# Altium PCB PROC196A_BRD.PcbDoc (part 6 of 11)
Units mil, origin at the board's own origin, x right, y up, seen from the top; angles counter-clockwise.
Board outline 3346.45 x 4921.26 mil, 8 copper layers (Top Layer, GND1, SIG1, PWR1, PWR2, SIG2, GND2, Bottom Layer), stack 54.534 mil thick; 736 components, 498 nets, 3030 pads, 1279 vias.
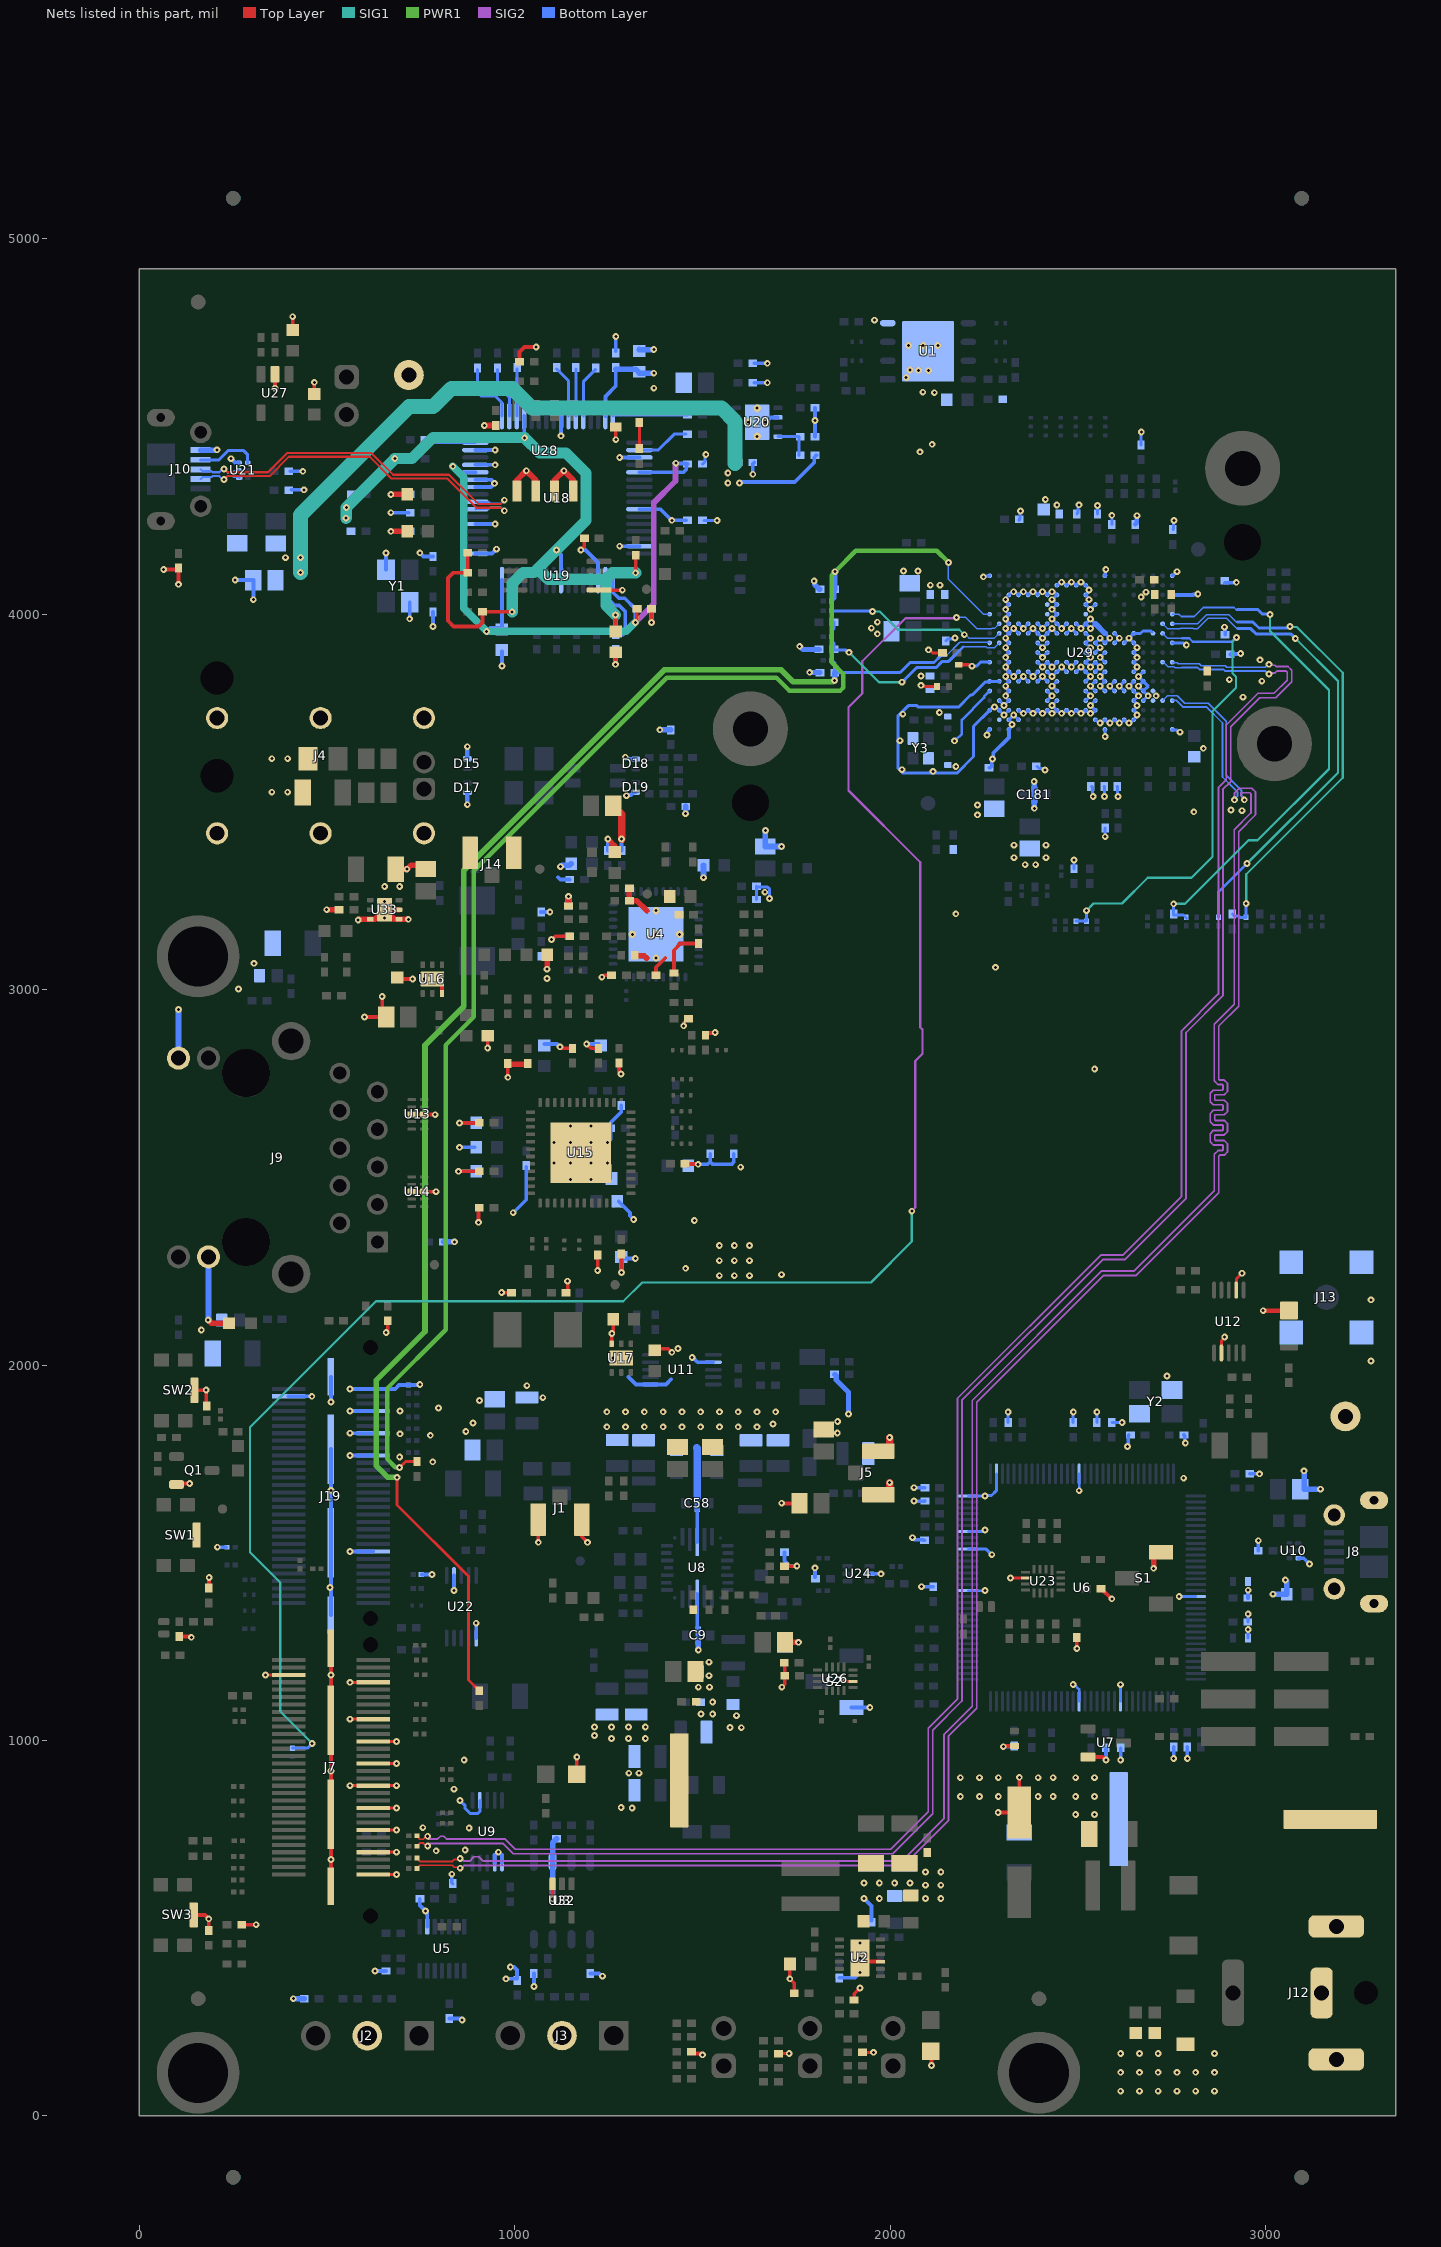
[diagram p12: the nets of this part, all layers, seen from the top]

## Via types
v1: diameter 18, hole 8, Top Layer to Bottom Layer, tented both sides, 1230 vias
v2: diameter 19.68, hole 7.87, Top Layer to Bottom Layer, 30 vias
v3: diameter 20, hole 10, Top Layer to Bottom Layer, tented both sides, 11 vias
v4: diameter 10, hole 4, SIG2 to Bottom Layer, tented both sides, 6 vias
v5: diameter 19.68, hole 7.87, Top Layer to Bottom Layer, tented both sides, 2 vias

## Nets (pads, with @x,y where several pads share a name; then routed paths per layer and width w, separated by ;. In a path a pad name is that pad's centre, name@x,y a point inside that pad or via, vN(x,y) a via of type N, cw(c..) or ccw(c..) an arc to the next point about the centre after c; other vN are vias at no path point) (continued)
FTDI_3V3: C87.1 C88.1 C89.1 C90.1 C91.1 L3.1 L4.1 R163.1 R181.2 R182.2 R184.2 R187.2 R201.2 U18.20 U18.31 U18.42 U18.50 U18.56 | length 2964.2
  Top Layer w10: R187.2@874.67,4164.3 R184.2@874.67,4110.53 835.5,4110.53 821.92,4096.95 821.92,3982.7 837.22,3967.39 903.42,3967.39 914.04,3978.01 R201.2@914.04,4006.75 v1(993.24,4006.75) ; v1(1268.73,3998.42) v1(1268.73,3998.42) C90.1@1268.76,3958.06 ; R181.2@1322.15,4153.61 1322.15,4110.61 v1(1322.22,4110.53)
  SIG1 w30: v1(550.51,4256.2) 551.26,4256.95 v1(551.26,4284.43) 680.38,4413.55 v1(680.38,4415.03) 726.22,4415.03 782.5,4471.31 1025.57,4471.31 v1(1026.57,4470.31) 1066.84,4430.04 1136.51,4430.04 1190.04,4376.52 1190.04,4250.38 v1(1111.12,4171.47) 1050.83,4111.18 1021.98,4111.18 993.24,4082.45 v1(993.24,4006.75) ; 1061.23,4121.58 1089.22,4093.59 1243.04,4093.59 ; v1(1268.73,3998.42) 1243.04,4024.11 1243.04,4093.59 ; v1(1322.22,4110.53) 1259.98,4110.53 1243.04,4093.59
  Bottom Layer w10: v1(680.38,4415.03) R163.1@717.82,4415.03 ; U18.20@1025.09,4528.19 1025.44,4527.84 1025.44,4471.44 v1(1026.57,4470.31) ; v1(1111.12,4171.47) 1123.51,4159.07 U18.56@1123.51,4091.18 ; U18.50@1241.62,4091.18 1241.62,4048.19 1266.15,4023.66 1278.4,4023.66 1294.53,4007.53 1294.53,3952.11 1288.67,3946.25 C91.1@1268.76,3946.25 ; U18.31@1241.62,4528.19 1241.62,4580.74 1269.17,4608.28 C88.1@1269.17,4653.39 ; v1(1268.73,3998.42) v1(1268.73,3998.42) C91.1@1268.76,3950.19 ; U18.42@1332.18,4280.16 1388.61,4280.16 v1(1418.39,4250.38) C89.1@1456.49,4250.38
  Bottom Layer w15: C88.1@1269.17,4653.39 1321.32,4653.39 1332.18,4642.54 v1(1370.48,4642.54)
  other v1: 1370.48,4602.54
FTDI_LDO_EN: R183.1 R204.2 U20.8 | length 105.6
  Bottom Layer w8: U20.8@1701.01,4473.42 1756.72,4473.42 R183.1@1756.72,4423.56
FTDI_MISO: R146.1 U18.18 | length 137.5
  Bottom Layer w8: R146.1@954.15,4652.62 954.15,4610 985.72,4578.44 U18.18@985.72,4528.19
FTDI_MOSI: R145.1 U18.17 | length 172.9
  Bottom Layer w8: R145.1@900.95,4652.65 900.95,4592.09 910.72,4582.33 947.43,4582.33 966.03,4563.72 U18.17@966.03,4528.19
FTDI_SPICLK: R144.1 U18.16 | length 133.4
  Bottom Layer w8: R144.1@765.07,4465.4 773.14,4457.32 U18.16@895.17,4457.32
FTDI_SPICS: R147.1 U18.19 | length 125.5
  Bottom Layer w8: U18.19@1005.4,4528.19 1005.4,4652.49 R147.1@1006.27,4653.35
FTDI_SUSPEND_N: R179.2 R180.2 | length 61.3
  Top Layer w8: R179.2@1332.18,4445.51 R180.2@1332.18,4506.81
FTDI_USBD_N: J10.2 U18.7 U21.1 | length 1029
  Top Layer w5.65: v1(225.33,4359.42) 225.91,4359.42 234.81,4368.32 346.93,4368.32 398.43,4419.81 613.58,4419.81 671.78,4361.61 820.78,4361.61 898.33,4284.06 962.68,4284.06 970.74,4276 v1(972.16,4276)
  Bottom Layer w5.65: J10.2@163.39,4360.62 168.43,4365.67 192.6,4365.67 195.25,4368.32 213.08,4368.32 221.98,4359.42 v1(225.33,4359.42) 225.91,4359.42 234.81,4368.32 249,4368.32 250.87,4366.45 263.61,4366.45 U21.1@265.99,4364.07 ; U18.7@895.17,4280.16 896.35,4281.34 931.78,4281.34 935.34,4284.9 962.68,4284.9 971.58,4276 v1(972.16,4276)
FTDI_USBD_P: J10.3 U18.8 U21.2 | length 1029.2
  Top Layer w5.65: v1(225.33,4387.42) 225.91,4387.42 234.81,4378.52 342.71,4378.52 394.2,4430.01 617.8,4430.01 676,4371.81 825,4371.81 902.55,4294.26 962.53,4294.26 972.16,4303.9 v1(972.16,4304)
  Bottom Layer w5.65: J10.3@163.39,4386.21 168.43,4381.16 192.6,4381.16 195.25,4378.52 213.08,4378.52 221.98,4387.42 v1(225.33,4387.42) 225.91,4387.42 234.81,4378.52 249,4378.52 251.85,4381.37 262.62,4381.37 U21.2@265.01,4383.75 ; U18.8@895.17,4299.84 896.35,4298.66 931.78,4298.66 935.34,4295.1 962.68,4295.1 971.58,4304 v1(972.16,4304)
FTDI_USBID: J10.4 U21.4 | length 161.5
  Bottom Layer w8: J10.4@163.39,4411.8 211.88,4411.8 236.13,4436.05 277.78,4436.05 288.63,4425.21 U21.4@288.63,4403.44
FTDI_VBUS: C39.1 C85.1 R183.2 R206.2 R207.2 U20.1 U20.2 | length 1842.6
  SIG1 w40: v1(429.39,4111.18) v1(429.39,4151.08) 429.39,4264.48 718.09,4553.18 782.4,4553.18 831.14,4601.93 993.63,4601.93 1045.37,4550.19 1550.62,4550.19 1587,4513.81 1587,4401.4
  Bottom Layer w10: v1@1598.67,4352.47 1745.8,4352.47 1797.91,4404.58 1797.91,4418.72 1802.75,4423.56 R183.2@1803.97,4423.56
  other v1: 389.39,4151.08 1567.54,4350.15 1598.67,4350.15 1567.54,4376.52
FTDI_VCORE: C77.1 C78.1 C79.1 C82.1 U18.12 U18.37 U18.49 U18.64 | length 1948.2
  Top Layer w10: v1(1321.38,3978.36) 1325.31,3982.29 C78.1@1325.31,4014.41
  SIG1 w20: v1(834.89,4394.53) 864.15,4365.27 864.15,4015.7 v1(925.28,3954.56) 1297.58,3954.56 v1(1321.38,3978.36)
  SIG2 w15: v1(1321.38,3978.36) 1370.48,4027.46 1370.48,4297.29 1428.43,4355.24 1428.43,4402.24 v1(1429,4402.81)
  Bottom Layer w10: v1(834.89,4394.53) 850.84,4378.58 U18.12@895.17,4378.58 ; v1(925.28,3954.56) 934.69,3963.97 965.97,3963.97 965.97,4091.11 U18.64@966.03,4091.18 ; U18.49@1261.31,4091.18 1261.31,4058.86 1277.42,4042.75 1293.04,4042.75 1321.38,4014.41 v1(1321.38,3978.36) ; U18.37@1332.18,4378.58 1449.8,4378.58 1457.06,4385.85 1457.06,4397.32 C82.1@1460.43,4400.69 ; v1(1429,4402.81) 1430.06,4401.75 1455.43,4401.75 C82.1@1456.49,4400.69
GND: C1.1 C2.1 C4.2 C5.1 C6.1 C7.2 C8.1 C9.2 C10.2 C11.1 C12.1 C13.1 C15.2 C16.1 C18.1 C20.1 C22.1 C23.2 C24.1 C25.2 C26.2 C27.1 C28.1 C29.2 C30.2 C31.2 C32.2 C33.2 C35.2 C36.1 C37.2 C38.2 C39.2 C40.2 C41.2 C42.1 C43.1 C44.2 C45.2 C46.1 C47.1 C48.2 C49.2 C50.2 C51.2 C52.2 C53.2 C54.1 C55.1 C56.2 C57.2 C58.2 C59.2 C60.2 C61.2 C62.2 C63.1 C64.1 C65.2 C66.1 C67.1 C68.2 C69.1 C70.2 C71.1 C72.2 C73.1 C74.1 C75.1 C76.1 C77.2 C78.2 C79.2 C80.2 C82.2 C83.2 C84.2 C85.2 C86.2 C87.2 C88.2 C89.2 C90.2 C91.2 C92.1 C93.2 C94.2 C95.2 C96.1 C97.2 C98.1 C99.2 C100.2 C101.2 C102.2 C103.2 C104.2 C105.1 C106.2 C107.1 C108.2 C109.1 C110.2 C111.1 C112.2 C113.1 C114.2 C115.1 C116.2 C117.1 C118.1 C119.2 C120.2 C121.2 C122.2 C125.2 C126.2 C127.2 C128.2 C129.2 C130.2 C131.1 C132.2 C133.2 C134.2 C135.1 C136.1 C137.1 C138.1 C139.1 C140.1 C141.1 C142.1 C143.2 C144.1 C145.2 C146.1 C147.2 C148.2 C149.1 C150.1 C151.2 C152.2 C153.1 C154.2 C155.1 C158.2 C159.2 C160.2 C163.1 C164.1 C165.1 C166.2 C167.2 C168.1 C169.2 C170.1 C171.2 C172.1 C173.1 C174.1 C175.1 C176.1 C177.1 C178.2 C180.2 C181.2 C182.2 C183.2 C184.2 C185.2 C186.2 C187.2 C188.2 C189.2 C190.2 C191.2 C192.2 C193.2 C194.2 C195.2 C196.2 C197.2 C198.2 C199.2 C200.2 C201.2 C202.2 D1.2 D3.1 D6.2 D8.2 D10.2 D12.2 D14.2 D15.2 D16.2 D17.2 D18.2 D19.2 J1.2 J1.3 J2.2 J3.2 J4.S1 J4.S2 J4.S3 J4.S4 J4.S5 J4.S6 J5.2 J5.3 J7.5 J7.8 J7.18 J7.24 J7.30 J7.36 J7.42 J7.48 J7.54 J7.60 J7.MP1 J7.MP2 J7.MP3 J7.MP4 J8.6 J8.9 J8.10 J8.11 J9.12 J9.13 J10.5 J12.2 J12.S1 J12.S2 J13.2 J14.2 J14.3 J19.16 J19.42 J19.48 J19.54 J19.57 J19.60 J19.MP1 J19.MP2 J19.MP3 J19.MP4 J21.1 J22.1 J23.1 NT1.1 NT2.2 NT3.2 NT4.2 Q1.2 R1.2 R2.1 R8.2 R10.1 R19.2 R79.1 R86.2 R89.2 R95.1 R97.1 R102.2 R110.1 R118.1 R119.2 R123.2 R126.2 R130.2 R137.1 R142.1 R143.1 R157.1 R172.1 R174.1 R175.1 R194.1 R196.2 R203.2 R204.1 R208.1 R209.1 R210.2 R251.1 R267.1 R282.1 R283.2 R285.1 R287.1 R288.1 R289.1 R292.1 R294.1 R296.2 R302.1 R303.1 R307.1 R312.1 R313.1 R314.1 R321.1 R326.1 R335.1 R337.2 R350.2 R400.2 R417.1 R512.2 S1.3 S2.3 SW1.5 SW2.5 SW3.5 TP7.1 TP9.1 U1.4 U1.9 U2.9 U2.13 U3.2 U4.37 U5.2 U6.10 U6.17 U6.48 U6.55 U6.58 U6.64 U6.66 U6.80 U6.114 U7.2 U8.12 U8.26 U9.1 U9.2 U9.7 U10.3 U11.1 U11.7 U12.2 U12.7 U13.3@725.63,2668.11 U13.8@758.51,2668.11 U14.3@725.63,2462.03 U14.8@758.51,2462.03 U15.49@1175.93,2565.54 U16.3 U16.7@780.58,3028.35 U17.3 U17.7@1283.94,2018.66 U18.1 U18.5 U18.10 U18.11 U18.13 U18.15 U18.25 U18.35 U18.47 U18.51 U19.5 U20.6 U20.9@1645.89,4511.81 U21.3 U22.1 U22.7 U23.6 U24.2 U26.6 U27.2 U28.1 U28.2 U28.3 U28.4 U29.A1 U29.A3 U29.A13 U29.A20 U29.B2 U29.B3 U29.B4 U29.B12 U29.B13 U29.B14 U29.B15 U29.B16 U29.C1 U29.C2 U29.C3 U29.C4 U29.C5 U29.C6 U29.C7 U29.C8 U29.C9 U29.C10 U29.C11 U29.C12 U29.C16 U29.D2 U29.D3 U29.D7 U29.D8 U29.D11 U29.D12 U29.D16 U29.D17 U29.D18 U29.E1 U29.E3 U29.E7 U29.E8 U29.E11 U29.E12 U29.E13 U29.E14 U29.E15 U29.E16 U29.E17 U29.E18 U29.F1 U29.F2 U29.F3 U29.F4 U29.F5 U29.F6 U29.F7 U29.F8 U29.F11 U29.F12 U29.F13 U29.F14 U29.F15 U29.F16 U29.F17 U29.G3 U29.G4 U29.G5 U29.G6 U29.G7 U29.G8 U29.G9 U29.G10 U29.G11 U29.G12 U29.G13 U29.G16 U29.G17 U29.H1 U29.H3 U29.H6 U29.H7 U29.H8 U29.H9 U29.H10 U29.H11 U29.H12 U29.H13 U29.H16 U29.J3 U29.J6 U29.J7 U29.J11 U29.J12 U29.J13 U29.J16 U29.K3 U29.K6 U29.K7 U29.K11 U29.K12 U29.K13 U29.K14 U29.K15 U29.K16 U29.K20 U29.L3 U29.L4 U29.L5 U29.L6 U29.L7 U29.L8 U29.L9 U29.L10 U29.L11 U29.L13 U29.L14 U29.L16 U29.L18 U29.M3 U29.M4 U29.M5 U29.M6 U29.M7 U29.M8 U29.M9 U29.M10 U29.M11 U29.M12 U29.N3 U29.N7 U29.N8 U29.N11 U29.P3 U29.P7 U29.P8 U29.P11 U29.P12 U29.R3 U29.R4 U29.R5 U29.R6 U29.R7 U29.R8 U29.R11 U29.R20 U29.T8 U29.T9 U29.T10 U29.T11 U29.U1 U29.U13 U29.U20 U32.3 U33.3 U33.4 U33.5 U33.7@653.41,3213.22 Y1.2 Y1.4 Y2.2 Y2.4 Y3.2 Y3.4 | length 18975.4
  Top Layer w7.5: v1(2320.48,1432.86) 2320.81,1432.53 2360.11,1432.53 U23.6@2360.3,1432.34
  Top Layer w8: v1(336.18,1174.67) J7.5@397.49,1174.67 ; v1@561.77,879.4 v1@684.4,879.4 ; v1@561.77,1056.56 J7.18@623.08,1056.56 ; v1@561.77,1154.99 J7.8@623.08,1154.99 ; J7.60@623.08,643.18 v1@684.4,643.18 ; J7.54@623.08,702.23 v1@684.4,702.23 ; J7.48@623.08,761.29 v1@684.4,761.29 ; J7.42@623.08,820.34 v1@684.4,820.34 ; J7.30@623.08,938.45 v1@684.4,938.45 ; J7.24@623.08,997.51 v1@684.4,997.51 ; R307.1@1702.27,165.74 v1(1731.14,165.74) ; v1(1871.6,1166.66) 1881.6,1156.66 U26.6@1901.26,1156.66 ; R313.1@1926.71,169.19 v1(1955.58,169.19) ; v1@2082,3807.81 C103.2@2125.25,3807.81 ; v1(2102.07,3905.43) 2104.77,3905.43 2113.37,3896.83 2138.81,3896.83 C180.2@2139.22,3897.25 ; C102.2@2182.53,3865.74 2211.37,3865.74 2215.29,3861.81 v1(2218,3861.81) ; U12.7@2882.66,2032.4 2882.66,2065.48 2891.36,2074.17 v1(2891.36,2074.78) ; U12.2@2922.03,2199.72 2922.38,2200.08 2922.38,2229.42 v1(2937.6,2244.64)
  Top Layer w10: v1(64.94,4119.21) 104.25,4119.21 v1(104.25,4079.89) ; Q1.2@99.01,1681.83 101.55,1684.36 v1(133.95,1684.36) ; C105.1@105.96,1276.96 136.4,1276.96 v1(138.5,1274.86) ; SW3.5@144.75,535.07 174.72,535.07 v1(184.83,524.96) R110.1@184.83,493.74 ; SW2.5@146.75,1932.78 v1@177.92,1932.78 ; v1(177.92,1933.44) v1@177.92,1932.78 ; R335.1@179.39,1891.44 177.92,1892.91 v1@177.92,1932.78 ; R267.1@185.16,1405.66 185.63,1406.13 185.63,1433.49 v1(186.1,1433.96) ; C128.2@276.53,509.12 v1(311.32,509.12) ; v1(361.36,4602.54) U27.2@361.36,4639.59 U27.2@361.36,4642.54 ; C145.2@408.44,4758.62 v1(408.44,4793.11) ; C149.1@466.12,4587.25 v1(466.12,4618.16) ; J7.MP4@510.29,611.09 v1(510.29,682.55) J7.MP3@510.29,803.61 v1(510.29,918.77) J7.MP2@510.29,1053.61 v1(510.29,1174.67) J7.MP1@510.29,1246.13 ; v1(599.63,2927.1) 647.02,2927.1 v1(647.02,2982.1) ; v1(657.49,2086.87) 661.43,2090.81 R118.1@661.43,2118.25 ; C48.2@687.02,3028.35 v1(728.16,3028.35) ; U14.3@725.63,2462.03 U14.8@758.51,2462.03 v1(790.24,2462.03) ; U13.3@725.63,2668.11 U13.8@758.51,2668.11 759.06,2667.55 787.45,2667.55 v1(788,2667) ; v2(802.23,3028.35) 806.17,3024.41 U16.3@806.17,2989.96 ; v1(850.52,2516.33) C188.2@901.41,2516.33 ; v1(853.06,2645.15) C189.2@901.41,2645.15 ; R337.2@901.41,2418.89 903.42,2416.88 v1(903.42,2380.25) ; v1@927.83,2842.39 v1(927.83,2844.44) R294.1@927.83,2877.21 ; C47.1@949.01,4503.22 C47.1@949.36,4503.22 ; v1(965.21,2193.37) 965.7,2192.88 987.22,2192.88 C33.2@987.71,2192.39 ; v1(981.5,2766.54) R97.1@981.5,2799.29 ; R417.1@1012.52,4672.69 1012.52,4699.22 1025.72,4712.43 v1(1057.2,4712.43) ; R137.1@1034.65,2799.29 R97.1@981.5,2799.29 ; R137.1@1034.65,2803.23 R97.1@981.5,2803.23 R97.1@981.5,2799.29 ; v1(1062.74,1527.76) J1.3@1062.74,1588.36 ; v1(1098,3133.81) 1100.16,3133.81 1108.56,3142.2 R89.2@1146.4,3142.2 ; U32.3@1100.33,617.88 1100.33,578.66 v1(1100.76,578.24) ; v1(1120.52,2847.77) 1124.45,2843.84 C160.2@1153.91,2843.84 ; v1(1140.83,2223.35) 1140.94,2223.24 C30.2@1140.94,2192.39 ; D16.2@1165.43,910.02 v1(1165.43,956.23) ; v1(1175.93,4171.47) 1185.46,4181 C86.2@1185.46,4202.72 ; J1.2@1178.88,1588.36 1178.88,1542.76 v1(1193.88,1527.76) ; v1(1191.71,2855.65) 1203.52,2843.84 C185.2@1223.15,2843.84 ; v1(1220.92,2252.12) C184.2@1220.92,2289.53 ; U19.5@1224.83,4064.47 v1(1286.74,4064.47) ; v1(1231.87,3033.39) 1236.87,3038.39 C36.1@1258.09,3038.39 ; U17.3@1258.35,2057.05 1258.35,2083.78 1262.45,2087.88 C65.2@1262.45,2122.43 ; v1(1268.76,3867.06) C90.2@1268.76,3899.01 ; v1(1269.17,4465.4) D1.2@1269.17,4499.01 ; R142.1@1277.72,2800.53 1277.72,2780.59 v1(1282.85,2775.46) ; v1@1284.2,2254.29 C191.2@1284.2,2291.7 ; C78.2@1364.68,4014.41 1364.68,3982.29 v1@1368.62,3978.36 ; C60.2@1373.01,2043.51 1408.88,2043.51 v1(1418.47,2033.92) ; C35.2@1376.2,3038.39 1376.2,3059.97 1400.81,3084.57 ; D10.2@1424,3044.53 1424,3105.14 1439.2,3120.34 1439.2,3122.96 1439.29,3122.86 C182.2@1489.66,3122.86 ; v1(1450.06,2903.88) 1451.59,2905.41 1451.59,2913.11 1461.28,2922.81 R79.1@1463.25,2922.81 ; C158.2@1453.86,2536.83 1454.86,2535.83 1487.63,2535.83 v1(1488.63,2534.83) ; R302.1@1471.02,171.07 1475.86,166.23 1494.15,166.23 1497.9,162.47 v1(1500.07,162.47) ; R289.1@1508.33,2878.66 1508.33,2879.63 1513.17,2884.47 1532.47,2884.47 v1(1534,2886) ; v1(1711.33,1632.06) 1711.83,1631.56 C198.2@1758.36,1631.56 ; v1(1711.55,1141.8) 1719.33,1149.58 C18.1@1719.33,1172.28 1719.33,1205.59 R283.2@1718.06,1206.86 ; R102.2@1718.74,1464.28 1718.8,1464.33 1751.57,1464.33 v1(1751.63,1464.39) ; C10.2@1732.73,404.47 v1(1732.73,365.1) 1744.54,353.29 R1.2@1744.54,326.87 ; R10.1@1904.25,308.55 1904.25,324.99 v1(1919.6,340.34) ; v2(1919.6,420.63) 1929.45,410.79 U2.9@1974.33,410.79 ; v1(2053,4651) v1@2053.5,4650.5 ; D12.2@2108.41,172.26 2110.15,170.52 v1(2110.15,134.17) ; v1(2287.98,808.05) C99.2@2344.16,808.05 v1(2344.16,901.82) ; v1(2301.76,983.22) 2303.71,985.16 C41.2@2330.38,985.16 ; v1@2497.52,1247.58 R296.2@2497.52,1274.04 ; U7.2@2527.23,956.1 2566.82,956.1 v1(2574.86,948.06) ; C98.1@2561.5,1403.8 2563.47,1403.8 2589.96,1377.31 v1(2590.79,1377.31)
  Top Layer w12: v1(2994,2144.81) 3062.14,2144.81 D6.2@3062.49,2145.16
  Top Layer w14: J5.2@1968.94,1770.93 1985.33,1770.93 J5.2@1999,1784.6
  Top Layer w15: v1(183.25,2119.9) 191.73,2111.42 D8.2@238.49,2111.42 ; v1(499.02,3213.22) R314.1@531.97,3213.22 ; v1(583.05,3185.43) 585.02,3187.4 587.09,3187.4 587.32,3187.63 U33.3@615.03,3187.63 627.82,3187.63 U33.7@653.41,3213.22 ; C197.2@669.98,3320.94 C197.2@683.13,3320.94 v1(712.61,3320.94) 723.59,3331.92 C196.2@763.1,3331.92 ; v1(669.98,4221.1) C68.2@713.89,4221.1 ; v1(669.98,4319.53) C72.2@713.89,4319.53 ; U33.5@691.8,3213.22 U33.7@653.41,3213.22 ; v1(716.55,3187.63) U33.4@691.8,3187.63 679,3187.63 U33.7@653.41,3213.22 ; v1(918.87,4503.22) C47.1@949.01,4503.22 ; U28.1@1005.83,4328.56 1005.83,4357.56 v1(1030.83,4382.56) 1055.83,4357.56 U28.2@1055.83,4328.56 ; v1(1086.18,3054.55) 1086.18,3056.06 1086.47,3056.35 C32.2@1086.47,3092.81 ; U28.3@1105.83,4328.56 1105.83,4357.56 v1(1130.83,4382.56) 1155.83,4357.56 U28.4@1155.83,4328.56 ; R350.2@1143.2,3222.97 v1(1143.2,3248.95) ; v1(1248.1,3401.21) 1266.14,3383.17 C147.2@1266.14,3366.46 ; C148.2@1305.51,3270.67 1305.51,3237.19 C154.2@1305.96,3236.75 1325.41,3236.75 1351.6,3210.56 ; D14.2@1319.63,3091.95 1320.72,3090.85 1344.05,3090.85 1350.33,3084.57 1351.6,3084.57 ; C120.2@1719.91,1261.41 v1(1756.11,1261.41) ; v1(2702.21,1458.6) 2702.21,1489.05 2714.4,1501.24 S1.3@2721.56,1501.24
  Top Layer w20: C122.2@1262.52,3489.89 1284.68,3467.73 v1(1284.68,3401.21) ; J5.3@1968.94,1654.79 1988.33,1654.79 1999,1665.46 v1(1999,1686.81) ; J5.2@1999,1784.6 v1(1999,1806.81)
  Bottom Layer w7: v1@2169.91,3664.72 2174.67,3664.72 2191.1,3681.16 2191.1,3719 2250.58,3778.48 2250.58,3781.16 U29.E1@2265.3,3795.89 ; U6.48@2208.34,1399.28 v1(2252.92,1399.28) ; v1@2487.86,1149.79 2489.39,1149.79 2503.61,1135.57 U6.17@2503.61,1104.01 ; v1(2503.61,1665.52) U6.80@2503.61,1710.31 ; U6.10@2613.85,1104.01 v1@2613.85,1147.29 ; v1@2771.35,1383.54 U6.114@2814.64,1383.54
  Bottom Layer w8: v1(854.27,840) 867.99,826.27 867.99,818.81 880.8,806 902.44,806 907.05,810.61 U9.7@907.05,840.58 ; C82.2@1499.8,4400.69 1500.91,4400.69 1506.6,4406.38 1506.6,4420.79 1509,4423.19 v1(1509,4425.81) ; C89.2@1503.74,4250.38 1503.83,4250.29 1539.14,4250.29 v1(1539.24,4250.19) ; C44.2@1643.95,3240.41 C46.1@1643.95,3275.88 1646.52,3273.31 1673.88,3273.31 1678.57,3268.62 v1(1678.57,3242.67) ; C115.1@2148.52,3929.27 2154.14,3934.9 2171.09,3934.9 v1(2173,3936.81) ; U6.55@2208.34,1509.52 2256.01,1509.52 2270.72,1494.81 v1(2271,1494.81) ; U6.58@2208.34,1556.77 2248.92,1556.77 v1(2252.92,1560.77) ; U6.64@2208.34,1651.25 v1(2252.92,1651.25) 2254.2,1652.53 2270.11,1652.53 2283.03,1665.45 2283.03,1682.64 2283.14,1682.75 U6.66@2283.14,1710.31 ; v1(2218,3861.81) 2218.7,3862.51 2230.99,3862.51 2241.14,3872.66 U29.H1@2265.3,3872.66 ; v1(2248.33,4100) 2250.21,4101.88 2263.83,4101.88 U29.U1@2265.3,4103.34 ; U29.D2@2290.89,3770.29 v1(2303.69,3757.5) U29.D3@2316.48,3770.29 2308.06,3778.72 v1(2308.06,3783.09) 2308.06,3787.46 U29.E3@2316.48,3795.89 2308.06,3804.31 v1(2308.06,3808.68) 2308.06,3813.05 U29.F3@2316.48,3821.48 2308.06,3829.9 v1(2308.06,3834.27) 2308.06,3838.64 U29.G3@2316.48,3847.07 ; U29.F2@2290.89,3821.48 U29.F1@2265.3,3821.48 2264.21,3820.38 2254.13,3820.38 2218.62,3784.87 2214.06,3784.87 2182,3752.81 2075.36,3752.81 2071.36,3756.81 2048.46,3756.81 2020.46,3728.81 2020.46,3591.21 2034.86,3576.81 2178,3576.81 2222.31,3621.12 2222.31,3701.72 U29.C1@2265.3,3744.7 2273.72,3753.13 v1(2278.1,3753.13) 2282.47,3753.13 U29.C2@2290.89,3744.7 v1(2303.69,3731.91) U29.C3@2316.48,3744.7 ; C49.2@2314.64,1847.1 v1(2314.64,1874.81) ; U29.A3@2316.48,3693.52 2324.91,3701.95 2324.91,3710.69 U29.B3@2316.48,3719.11 v1(2329.28,3731.91) U29.B4@2342.07,3719.11 ; U29.C4@2342.07,3744.7 2350.5,3736.28 v1(2354.87,3736.28) 2359.24,3736.28 U29.C5@2367.66,3744.7 2376.09,3736.28 v1(2380.46,3736.28) 2384.83,3736.28 U29.C6@2393.25,3744.7 2401.68,3736.28 v1(2406.05,3736.28) 2410.42,3736.28 U29.C7@2418.84,3744.7 2427.27,3736.28 v1(2431.64,3736.28) 2436.01,3736.28 U29.C8@2444.43,3744.7 ; U29.F4@2342.07,3821.48 v1(2354.87,3834.27) U29.F5@2367.66,3821.48 ; U29.G4@2342.07,3847.07 v1(2329.28,3834.27) U29.G3@2316.48,3847.07 ; U29.L4@2342.07,3949.43 v1(2329.28,3962.22) U29.L3@2316.48,3949.43 ; U29.M4@2342.07,3975.02 v1(2354.87,3962.22) U29.M5@2367.66,3975.02 ; C150.1@2343.16,4249.83 C150.1@2345.15,4251.81 ; C150.1@2343.97,4253 2345.62,4254.66 2345.62,4273.93 v1(2347.28,4275.59) ; U29.G5@2367.66,3847.07 v1(2380.46,3834.27) U29.G6@2393.25,3847.07 ; U29.L5@2367.66,3949.43 v1(2380.46,3962.22) U29.L6@2393.25,3949.43 v1(2406.05,3936.63) U29.L7@2418.84,3949.43 v1(2431.64,3962.22) U29.L8@2444.43,3949.43 ; C117.1@2391.37,3595.05 2397.19,3589.24 2406.29,3589.24 2410.11,3585.42 v1(2412.82,3585.42) ; U29.F6@2393.25,3821.48 v1(2406.05,3834.27) U29.F7@2418.84,3821.48 ; U29.H6@2393.25,3872.66 v1(2406.05,3859.86) U29.H7@2418.84,3872.66 v1(2431.64,3859.86) U29.H8@2444.43,3872.66 ; U29.J6@2393.25,3898.25 v1(2406.05,3885.45) U29.J7@2418.84,3898.25 ; U29.K6@2393.25,3923.84 v1(2406.05,3911.04) U29.K7@2418.84,3923.84 ; U29.M6@2393.25,3975.02 v1(2406.05,3962.22) U29.M7@2418.84,3975.02 ; U29.D7@2418.84,3770.29 v1(2431.64,3783.09) U29.E7@2418.84,3795.89 ; U29.G7@2418.84,3847.07 v1(2431.64,3834.27) U29.G8@2444.43,3847.07 v1(2457.23,3859.86) U29.G9@2470.03,3847.07 ; U29.D8@2444.43,3770.29 v1(2431.64,3757.5) U29.C8@2444.43,3744.7 ; U29.E8@2444.43,3795.89 v1(2431.64,3808.68) U29.F8@2444.43,3821.48 ; U29.T8@2444.43,4077.38 2452.86,4085.81 v1(2457.23,4085.81) 2461.6,4085.81 U29.T9@2470.03,4077.38 2478.45,4085.81 v1(2482.82,4085.81) 2487.19,4085.81 U29.T10@2495.62,4077.38 2504.04,4085.81 v1(2508.41,4085.81) 2512.78,4085.81 U29.T11@2521.21,4077.38 2529.63,4068.96 v1(2529.63,4064.59) 2529.63,4060.21 U29.R11@2521.21,4051.79 2529.63,4043.37 v1(2529.63,4039) 2529.63,4034.62 U29.P11@2521.21,4026.2 v1(2534,4013.4) U29.P12@2546.8,4026.2 ; U29.H9@2470.03,3872.66 v1(2482.82,3859.86) U29.H10@2495.62,3872.66 ; U29.L9@2470.03,3949.43 v1(2482.82,3962.22) U29.L10@2495.62,3949.43 ; U29.M9@2470.03,3975.02 v1(2457.23,3962.22) U29.M8@2444.43,3975.02 v1(2431.64,3987.81) U29.N8@2444.43,4000.61 v1(2431.64,4013.41) U29.P8@2444.43,4026.2 v1(2431.64,4039) U29.R8@2444.43,4051.79 2436.01,4060.21 v1(2431.64,4060.21) 2427.27,4060.21 U29.R7@2418.84,4051.79 2410.42,4060.21 v1(2406.05,4060.21) 2401.68,4060.21 U29.R6@2393.25,4051.79 2384.83,4060.21 v1(2380.46,4060.21) 2376.09,4060.21 U29.R5@2367.66,4051.79 2359.24,4060.21 v1(2354.87,4060.21) 2350.5,4060.21 U29.R4@2342.07,4051.79 2333.65,4060.21 v1(2329.28,4060.21) 2324.91,4060.21 U29.R3@2316.48,4051.79 2308.06,4043.37 v1(2308.06,4039) 2308.06,4034.62 U29.P3@2316.48,4026.2 2308.06,4017.78 v1(2308.06,4013.4) 2308.06,4009.03 U29.N3@2316.48,4000.61 2308.06,3992.19 v1(2308.06,3987.81) 2308.06,3983.44 U29.M3@2316.48,3975.02 2308.06,3966.59 v1(2308.06,3962.22) 2308.06,3957.85 U29.L3@2316.48,3949.43 ; C42.1@2487.6,1847.1 2487.8,1847.3 2487.8,1874.61 v1(2488,1874.81) ; R303.1@2489.92,3322.25 2489.96,3322.29 v1(2489.96,3345.77) ; U29.G10@2495.62,3847.07 v1(2508.41,3859.86) U29.G11@2521.21,3847.07 v1(2534,3834.27) U29.F11@2521.21,3821.48 ; U29.M10@2495.62,3975.02 v1(2508.41,3962.22) U29.M11@2521.21,3975.02 ; C92.1@2497.58,4267.83 2501.09,4271.34 2501.09,4289.9 v1(2503,4291.81) ; U29.D11@2521.21,3770.29 v1(2534,3783.09) U29.E11@2521.21,3795.89 ; U29.L11@2521.21,3949.43 v1(2534,3936.63) U29.K11@2521.21,3923.84 v1(2534,3911.04) U29.J11@2521.21,3898.25 v1(2534,3885.45) U29.H11@2521.21,3872.66 v1(2534,3859.86) U29.H12@2546.8,3872.66 v1(2559.59,3859.86) U29.G12@2546.8,3847.07 ; C140.1@2537.04,3541.71 2539.09,3539.67 2539.09,3516.72 v1(2541,3514.81) ; U29.B12@2546.8,3719.11 2555.22,3710.69 v1(2559.59,3710.69) 2563.96,3710.69 U29.B13@2572.39,3719.11 2580.81,3710.69 v1(2585.18,3710.69) 2589.55,3710.69 U29.B14@2597.98,3719.11 2606.4,3710.69 v1(2610.77,3710.69) 2615.14,3710.69 U29.B15@2623.57,3719.11 2631.99,3710.69 v1(2636.36,3710.69) 2640.74,3710.69 2657.58,3727.54 v1(2657.58,3731.91) 2657.58,3736.28 U29.C16@2649.16,3744.7 2657.58,3753.13 v1(2657.58,3757.5) 2657.58,3761.87 U29.D16@2649.16,3770.29 v1(2661.96,3783.09) U29.E16@2649.16,3795.89 ; U29.D12@2546.8,3770.29 v1(2534,3757.5) U29.C12@2546.8,3744.7 2538.37,3736.28 v1(2534,3736.28) 2529.63,3736.28 U29.C11@2521.21,3744.7 2512.78,3736.28 v1(2508.41,3736.28) 2504.04,3736.28 U29.C10@2495.62,3744.7 2487.19,3736.28 v1(2482.82,3736.28) 2478.45,3736.28 U29.C9@2470.03,3744.7 2461.6,3736.28 v1(2457.23,3736.28) 2452.86,3736.28 U29.C8@2444.43,3744.7 ; U29.E12@2546.8,3795.89 v1(2534,3808.68) U29.F12@2546.8,3821.48 ; U29.J12@2546.8,3898.25 v1(2559.59,3911.04) U29.K12@2546.8,3923.84 v1(2559.59,3936.63) U29.K13@2572.39,3923.84 v1(2585.18,3936.63) U29.L13@2572.39,3949.43 ; C74.1@2550.86,1847.1 v1(2550.86,1874.81) ; C164.1@2552.55,4267.83 v1(2552.55,4289.88) ; C163.1@2570.08,3541.71 2570.54,3541.25 2570.54,3515.27 v1(2571,3514.81) ; U29.A13@2572.39,3693.52 2572.69,3693.22 2572.69,3675.12 v1(2573,3674.81) ; U29.E13@2572.39,3795.89 v1(2559.59,3808.68) U29.F13@2572.39,3821.48 v1(2559.59,3834.27) U29.G13@2572.39,3847.07 ; U29.H13@2572.39,3872.66 v1(2559.59,3885.45) U29.J13@2572.39,3898.25 ; R312.1@2572.88,3430.44 2572.95,3430.37 2572.95,3407.78 v1(2573.02,3407.71) ; C75.1@2590.64,1847.1 v1(2618.35,1847.1) ; C174.1@2590.78,4239.83 v1(2590.78,4263.81) ; U29.E14@2597.98,3795.89 v1(2585.18,3808.68) U29.F14@2597.98,3821.48 ; U29.K14@2597.98,3923.84 v1(2610.77,3936.63) U29.L14@2597.98,3949.43 ; C175.1@2605.12,3541.71 2606.06,3540.77 2606.06,3515.75 v1(2607,3514.81) ; U29.E15@2623.57,3795.89 v1(2610.77,3808.68) U29.F15@2623.57,3821.48 ; U29.K15@2623.57,3923.84 v1(2636.36,3936.63) ; U29.E16@2649.16,3795.89 v1(2636.36,3808.68) U29.F16@2649.16,3821.48 ; U29.G16@2649.16,3847.07 2657.58,3855.49 v1(2657.58,3859.86) 2657.58,3864.23 U29.H16@2649.16,3872.66 2657.58,3881.08 v1(2657.58,3885.45) 2657.58,3889.82 U29.J16@2649.16,3898.25 2657.58,3906.67 v1(2657.58,3911.04) 2657.58,3915.41 U29.K16@2649.16,3923.84 v1(2636.36,3936.63) ; R326.1@2668.4,4451.58 2668.75,4451.94 2668.75,4485.39 v1(2669.11,4485.75) ; U29.D17@2674.75,3770.29 v1(2687.55,3783.09) U29.E17@2674.75,3795.89 ; U29.G17@2674.75,3847.07 v1(2661.95,3834.27) U29.F17@2674.75,3821.48 ; U29.L18@2697.55,3953.5 2695.33,3955.72 2673.67,3955.72 2667.38,3949.43 U29.L16@2649.16,3949.43 v1(2636.36,3936.63) ; U29.A20@2751.52,3693.52 2752.62,3692.43 2763.36,3692.43 2769.78,3686 v1(2772.49,3686) ; U29.K20@2751.52,3923.84 2752.05,3923.31 2782.28,3923.31 2786.54,3919.05 v1@2789.82,3919.05 ; U29.U20@2751.52,4102.97 2752.75,4102.97 2763.36,4113.58 v1(2764.59,4113.58) ; C165.1@2753.34,4225.68 2754.68,4227.02 2754.68,4248.66 v1(2756.02,4250) ; C64.1@2952.87,1315.66 2953.44,1316.23 2953.44,1336.25 v1(2954,1336.81) ; C62.2@2953.5,1272.74 2953.73,1272.96 2953.73,1295.49 v1(2953.95,1295.72) ; U29.G3@2316.48,3847.07 2308.06,3855.49 v1(2308.06,3859.86) 2308.06,3864.23 U29.H3@2316.48,3872.66 2308.06,3881.08 v1(2308.06,3885.45) 2308.06,3889.82 U29.J3@2316.48,3898.25 2308.06,3906.67 v1(2308.06,3911.04) 2308.06,3915.41 U29.K3@2316.48,3923.84 2308.06,3932.26 v1(2308.06,3936.63) 2308.06,3941 U29.L3@2316.48,3949.43 ; U29.M11@2521.21,3975.02 v1(2534,3962.22) U29.M12@2546.8,3975.02 v1(2534,3987.81) U29.M11@2521.21,3975.02 ; U29.E17@2674.75,3795.89 2687.55,3808.68 U29.F17@2674.75,3821.48 ; U29.E17@2674.75,3795.89 v1(2661.95,3808.68) U29.F17@2674.75,3821.48
  Bottom Layer w10: v1(207.63,1514.71) R321.1@231.46,1514.71 ; v1(243.95,4414.8) 254.41,4404.34 264.1,4404.34 U21.3@265.01,4403.44 ; v1(255.13,4091.18) C39.2@303.71,4091.18 303.71,4038.7 v1(303.4,4039.01) ; v1(264.08,3002.19) v1@264.25,3002.19 ; J19.57@397.49,1916.88 v1@458.81,1916.88 ; R208.1@401.87,4381.16 v1(435.53,4381.16) ; C97.2@405.07,4331.74 v1(438.72,4331.74) ; J19.MP1@510.29,1333.61 510.29,1402.34 507.56,1405.07 v1(507.56,1407.23) 507.56,1409.4 510.29,1412.13 J19.MP2@510.29,1526.13 v1(510.29,1666.52) J19.MP3@510.29,1776.13 ; v1(510.29,1901.57) J19.MP4@510.29,1968.65 ; v1@561.77,1503.49 J19.16@623.08,1503.49 ; v1@561.77,1759.4 J19.42@623.08,1759.4 ; v1@561.77,1818.45 J19.48@623.08,1818.45 ; v1@561.77,1877.51 J19.54@623.08,1877.51 ; v1@561.77,1936.56 J19.60@623.08,1936.56 681.53,1936.56 691.81,1946.85 R196.2@716.86,1946.85 v1@746.99,1946.85 ; v1(627.93,385.8) R19.2@657.14,385.8 ; Y1.2@657.29,4118.74 v1(657.29,4163.55) ; v1(669.98,4221.1) C69.1@717.82,4221.1 ; v1(669.98,4270.79) R157.1@717.82,4270.79 ; v1(669.98,4319.53) C73.1@717.82,4319.53 ; v1(720.28,3987.99) Y1.4@720.28,4032.13 ; v1(747.04,4164) 756.86,4154.17 C83.2@782.36,4154.17 ; C11.1@747.25,578.34 747.25,560.09 v1(762,545.34) 766.94,540.4 U5.2@766.94,503.91 ; R512.2@753.28,1441.92 v1(779.8,1441.92) ; v1(782.36,3967.39) C84.2@782.36,4006.54 ; R400.2@810.21,2327.93 R400.2@810.78,2328.51 ; C80.2@825.99,259.18 856.01,259.18 v1(859.95,255.24) ; v1(832.48,643.68) 832.48,620.63 C12.1@834.66,618.46 ; v1@838.18,1399.86 U22.7@838.18,1439.7 ; v1(850.52,2516.33) C59.2@890.99,2516.33 ; v1(853.06,2580.18) C56.2@893.54,2580.18 ; v1(853.06,2645.15) C187.2@893.54,2645.15 ; U18.1@895.17,4162.05 939.67,4162.05 v1(951.35,4173.72) ; U18.5@895.17,4240.79 v1(947.85,4240.79) ; U18.10@895.17,4339.21 936.51,4339.21 v1(946.35,4349.06) 936.51,4358.9 U18.11@895.17,4358.9 ; U18.13@895.17,4398.27 v1(947.85,4398.27) ; U18.15@895.17,4437.64 v1(947.85,4437.64) ; U22.1@897.24,1272.38 897.24,1312.22 v1(897.44,1312.42) ; U9.2@946.42,673.26 946.42,694.81 952.43,700.81 955.31,700.81 956.12,700 956.93,700.81 959.82,700.81 966.11,694.52 U9.1@966.11,673.26 ; v1(965.97,3862.6) C79.2@965.97,3900.98 ; v1(977,364.82) 1006.26,364.82 1006.26,388.28 998.07,396.47 v1(988.14,396.47) ; v1(996.01,2405.89) 1030.83,2440.71 C57.2@1030.83,2527.47 ; R86.2@1050.93,379.29 1051.06,379.16 1051.06,344.29 v1(1051.19,344.16) ; C121.2@1070.29,3206.84 v1(1093.48,3206.84) ; C159.2@1078.54,2855.52 1112.77,2855.52 v1(1120.52,2847.77) ; 1115.27,3299.62 1121.18,3293.72 R251.1@1146.4,3293.72 ; v1@1123.51,4477.01 U18.25@1123.51,4528.19 ; v1(1175.93,4171.47) 1188.71,4171.47 1221.94,4138.24 U18.51@1221.94,4091.18 ; v1(1191.71,2855.65) C53.2@1223.15,2855.65 ; C20.1@1200.93,379.29 1224.17,379.29 1231.6,371.87 v1(1233.72,371.87) ; v2(1246.79,2538.57) 1253.52,2531.85 C192.2@1253.52,2497.07 ; v2(1246.79,2592.51) 1255.64,2601.35 C193.2@1255.64,2630.46 1255.64,2646.63 1284.09,2675.08 R143.1@1284.09,2691.56 ; C54.1@1248.1,3370.12 C54.1@1248.1,3370.47 v1(1248.1,3401.21) ; v1(1268.76,3867.06) C91.2@1268.76,3906.88 ; C88.2@1269.17,4700.64 v1(1269.17,4740.26) ; C183.2@1276.86,2436.07 1307.04,2405.89 1307.04,2397.74 v1(1316.79,2387.99) ; v1(1279.5,4181.73) U18.47@1332.18,4181.73 ; v1(1279.5,4417.95) U18.35@1332.18,4417.95 ; v1(1284.2,2246.79) 1284.2,2283.82 v1(1321.22,2283.82) ; C52.2@1284.68,3370.12 C52.2@1284.68,3370.47 v1(1284.68,3401.21) ; v1(1294.6,3619.41) 1299.68,3614.34 D18.2@1322.29,3614.34 ; v1(1298,3517) 1299.53,3518.53 1309.71,3518.53 1317.36,3526.19 D19.2@1322.29,3526.19 ; 1303.03,1968.41 1322.97,1948.48 U11.1@1361.7,1948.48 1403.09,1948.48 1416.7,1962.09 ; v1(1364.68,3978.36) C77.2@1364.68,4014.41 ; C186.2@1462.14,2531.54 1465.43,2534.83 v1(1488.63,2534.83) 1513.77,2534.83 1520.83,2541.89 ; v1(1472.73,2019.91) 1474.89,2019.91 1487.27,2007.53 U11.7@1529.02,2007.53 ; U8.12@1486.13,1390.85 1486.13,1298.24 C9.2@1489.02,1295.35 ; U8.26@1486.13,1528.64 C58.2@1486.12,1616.32 ; R287.1@1520.83,2562.86 1520.83,2541.89 ; R288.1@1583.69,2562.91 1583.69,2541.25 1577.15,2534.71 1528,2534.71 1520.83,2541.89 ; v1(1634.31,4373.24) 1634.19,4373.35 1634.19,4400.74 C85.2@1638.02,4404.56 ; C93.2@1638.02,4617.01 v1(1673.01,4617.01) ; C94.2@1638.02,4668.86 v1(1673.01,4668.86) ; v2(1668.53,4511.81) 1681.33,4524.6 U20.6@1701.01,4524.6 ; R292.1@1718.74,1501.05 1718.74,1478.91 1733.37,1464.28 1751.52,1464.28 v1(1751.63,1464.39) ; C133.2@1799.69,1435.2 v1(1799.69,1459.75) ; R204.1@1800.03,4473.42 v1(1800.03,4516.46) R203.2@1800.03,4550.19 ; R2.1@1864.88,367.48 1905.83,367.48 v2(1919.6,381.26) ; S2.3@1897.32,1087.76 v1(1945.88,1087.76) ; v1(1930.47,579.21) 1950.73,558.95 R8.2@1950.73,520.51 ; U24.2@1945.05,1443.85 v1(1975.6,1443.85) ; v1(2059.43,1540) 2060.18,1539.28 2064.91,1534.55 2088.27,1533.77 R194.1@2091.99,1533.4 ; v1@2063.71,1637.54 R126.2@2092.58,1637.75 ; v1@2063.71,1673.14 R123.2@2092.58,1673.35 ; v1@2083.46,1409.65 C50.2@2114.73,1409.65 ; v1(2258.33,3678.3) 2259.86,3679.83 2259.86,3687.08 2265.3,3692.52 U29.A1@2265.3,3693.52 ; C168.1@2263.91,3591.08 2265.88,3591.08 2270.72,3595.93 2270.72,3610.37 2273,3612.65 v1(2273,3614.81) 2274.53,3616.34 2274.53,3630.07 2316.48,3672.02 U29.A3@2316.48,3693.52 ; v1(2301.76,983.22) 2304.02,985.48 C76.1@2330.38,985.48 ; v1@2306.76,983.22 C76.1@2330.38,983.22 ; U29.U13@2572.39,4102.97 2572.39,4103.98 2573.1,4104.69 2573.1,4115.81 2574.68,4117.39 v1(2574.68,4119.55) ; v1(2574.86,948.06) C67.1@2574.86,978.71 ; v1(2614.2,948.06) C66.1@2614.2,978.71 ; v1(2632.75,1783.19) 2634.28,1784.72 2634.28,1811.89 C70.2@2636.03,1813.63 ; U29.R20@2751.52,4051.79 2806.88,4051.79 2808.06,4052.97 2818.16,4052.97 v1(2819.69,4054.5) ; v1(2755.58,951.98) R285.1@2755.58,982.63 ; C63.1@2783.14,1813.63 2785.07,1811.7 2785.07,1793.97 v1(2786.6,1792.44) ; v1(2791.65,952) C109.1@2791.65,982.63 ; v1(2891,3965.81) 2892.69,3965.81 2892.84,3965.65 2892.84,3945.97 C170.1@2892.69,3945.81 ; C177.1@2891.24,4084.07 2891.37,4083.94 2920.87,4083.94 2922.16,4085.23 v1(2922.42,4085.23) ; C176.1@2906.17,3893.25 2907.55,3894.62 2925.19,3894.62 2932.48,3894.62 v1(2933.86,3896) ; C43.1@2953.19,1379.55 2953.43,1379.8 2953.43,1399.61 v1(2953.99,1400.17) ; C71.1@2958.29,1710.31 v1(2984.1,1710.31) ; R174.1@2980.81,1505.18 v1@2980.81,1531.46 ; U10.3@3087.63,1485.5 3101.82,1485.5 v1(3117.06,1470.26)
  Bottom Layer w12: v1(873.77,3493.07) D17.2@873.77,3525.15 ; D15.2@873.77,3615.37 v1(873.77,3647.45) ; C96.1@2653.45,4239.83 2656.85,4243.23 2656.85,4261.66 v1(2658,4262.81)
  Bottom Layer w14: v1(1759,3914.81) 1760.08,3914.81 1768.32,3906.58 C136.1@1810.99,3906.58 ; v1(1785.89,3845.61) 1786.27,3845.23 1812.72,3845.23 C135.1@1813.1,3844.85 ; v1(1797.69,4088.81) 1798.46,4088.05 1798.46,4079.67 1811.13,4066.99 C131.1@1813.1,4066.99 ; R172.1@1851.72,1975.11 1853.69,1975.11 1856.53,1972.27 1856.53,1960.21 1889,1927.74 v1(1889,1869.81) ; v1(2383.91,3554.57) 2384.03,3554.45 2384.03,3535.44 C181.2@2384.16,3535.31 C181.2@2384.16,3503.82 v1(2384.16,3483.18)
  Bottom Layer w15: J9.12@104.25,2817.7 v1(104.25,2946.96) ; J10.5@163.39,4437.39 205.95,4437.39 v1(207.01,4438.45) ; v1(183.25,2119.9) 184.18,2120.83 J9.13@184.18,2288.17 ; v1(410.2,311.94) C13.1@439.12,311.94 ; R400.2@810.78,2328.51 v1(839.7,2328.51) ; v1(1100.76,578.24) 1100.76,620.31 1100.76,627.57 1100.93,627.73 1100.93,727.53 C16.1@1111.56,738.16 ; v1(1121.94,3327.81) 1122.75,3327.81 1126.06,3331.12 1145.65,3331.12 C51.2@1150.55,3336.02 ; C55.1@1143.2,3222.97 v1(1143.2,3248.95) ; C87.2@1332.18,4705.53 1332.43,4705.28 v1(1370.48,4705.28) ; v1(1386.65,3692.29) C155.1@1415.62,3692.29 ; v1(1455.09,3468.79) 1455.32,3469.02 1455.32,3487.94 C166.2@1455.55,3488.17 ; C58.2@1486.12,1616.32 C58.2@1486.12,1647.81 ; v1(1489.02,1241.22) C9.2@1489.02,1263.85 C9.2@1489.02,1295.35 ; v1(1502.85,3298.52) C40.2@1502.85,3331.1 ; v1(1667.73,3424.12) C37.2@1667.73,3381.69 v1(1710.49,3381.69) ; U29.M12@2546.8,3975.02 U29.L13@2572.39,3949.43 ; v1(3020.18,1389.64) 3020.29,1389.75 R175.1@3056.95,1389.75 3056.95,1423.82 v1(3053.01,1427.76) ; v1(3102.88,1718.35) 3102.92,1718.3 3102.92,1669.54 3127.92,1669.54 3128.05,1669.42 v1(3146.51,1669.42)
  Bottom Layer w20: 1485.15,1779.09 1486.12,1778.11 C58.2@1486.12,1647.81
  other v1: 2614.2,65.74 2664.2,65.74 2714.2,65.74 2764.2,65.74 2814.2,65.74 2864.2,65.74 2614.2,115.74 2664.2,115.74 2714.2,115.74 2764.2,115.74 2814.2,115.74 2864.2,115.74 2614.2,165.74 2664.2,165.74 2714.2,165.74 2864.2,165.74 1971.38,579.21 2094.14,579.21 2135.06,579.21 2094.14,614.39 2135.06,614.39 1930.47,620.13 1971.38,620.13 2012.3,620.13 2053.22,620.13 684.8,643.18 2094.14,649.3 2135.06,649.3 684.8,702.23 956.12,702.34 790.71,706.06 867.99,708.22 684.8,761.29 878.73,767 755.1,767.48 2494.54,802.8 2544.54,802.8 1312.84,819.92 684.8,820.34 1283.45,821.43 2186.98,850.8 2238.45,850.8 2288.45,850.8 2394.54,850.8 2434.54,850.8 2494.54,850.8 2544.54,850.8 838.47,870 561.37,879.4 684.8,879.4 2186.98,900.8 2238.45,900.8 2288.45,900.8 2394.54,900.8 2434.54,900.8 2494.54,900.8 2544.54,900.8 1303.98,912.69 1331.33,912.69 684.8,938.45 865.42,947.89 684.8,997.51 1257.75,1005.05 1302.75,1005.05 1347.75,1005.05 1212.75,1013.05 1603.73,1034.11 1573.59,1034.31 1212.75,1035.66 1257.75,1035.66 1302.75,1035.66 1347.75,1035.66 561.37,1056.56 1590.73,1066.09 1496.16,1070.27 1527.52,1070.27 1527.52,1102.22 1489.02,1141.8 1519.02,1141.8 2487.86,1149.29 2613.85,1148.59 561.37,1154.99 1517.26,1172.41 1517.26,1208.42 2497.52,1245.18 2770.05,1383.54 837.98,1399.65 2083.43,1409.68 561.27,1503.49 2980.84,1532.09 2063.34,1637.75 2063.34,1673.35 2782,1698.81 781.59,1742.35 693.64,1754.94 561.27,1759.4 775,1812.81 694.18,1816.96 561.27,1818.45 1859.23,1819 869.52,1823 1245.36,1835.66 1295.36,1835.66 1345.36,1835.66 1395.36,1835.66 1445.36,1835.66 1495.36,1835.66 1545.36,1835.66 1595.36,1835.66 1645.36,1835.66 1688.22,1842.8 889,1845.97 1860.39,1850 1245.36,1875.66 1295.36,1875.66 1345.36,1875.66 1395.36,1875.66 1445.36,1875.66 1495.36,1875.66 1545.36,1875.66 1595.36,1875.66 1645.36,1875.66 1695.36,1875.66 561.27,1877.51 694.18,1877.51 796.77,1885.48 906,1905.87 1074.72,1913.24 459.31,1916.88 561.27,1936.56 1032.32,1945.2 746.99,1948.35 2738,1970.81 3281,2010.81 1435,2044.31 1258.68,2083.95 165.06,2093.51 3281,2173.81 1545.12,2238.24 1585.12,2238.24 1625.12,2238.24 1710.91,2240.91 1455.5,2257.81 1545.12,2278.24 1585.12,2278.24 1625.12,2278.24 1545.12,2318.24 1585.12,2318.24 1625.12,2318.24 1478.32,2385.05 1602,2527.31 2545,2788.81 1086,3029.81 2281,3059.81 305.37,3070.35 2175.12,3202.05 1666.09,3259.92 653.41,3274.98 693.41,3274.98 2359.99,3333.05 2387.99,3333.05 2329.89,3351.77 2415.09,3351.77 2329.99,3385.05 2415.09,3385.05 2232.74,3465.81 2809,3473.81 2937.61,3477 2908.09,3479 2233.09,3491.81 352.96,3526.19 395.06,3526.19 2114,3581.81 2031.95,3586.09 2175,3594.81 352.96,3615.37 395.06,3615.37 2834.42,3643 2171.4,3663.21 2026.46,3663.49 2324.91,3706.32 2033.96,3734.16 2131,3738.81 2940.27,3779.2 2708.76,3783.09 2082,3810.81 2990.35,3822 2903.54,3826 2082,3835.75 2985.6,3879 2789.26,3918.49 1966,3948 1950,3963 1966,3979 2668.96,4046 2682.05,4059.09 2107,4077.81 2133,4077.81 2036,4115.81 2074,4115.81 2444,4291.31 2413.35,4306 2080,4433 2112,4453 1123.51,4475.51 2117.63,4590.49 2087,4592 2043,4631 2102,4649 2076,4650 2049,4716 2088,4716 2127,4716 1958.66,4783.66
  other v2: 1919.6,460 1262.29,2018.66 1305.59,2018.66 1148.96,2494.68 1202.9,2494.68 1105.06,2538.57 1148.96,2538.57 1202.9,2538.57 1105.06,2592.51 1148.96,2592.51 1202.9,2592.51 1148.96,2636.41 1202.9,2636.41 758.93,3028.35 1376.2,3084.57 1313.21,3147.56 1376.2,3147.56 1439.2,3147.56 653.41,3191.57 1376.2,3210.56 653.41,3234.88 1645.89,4474.41 1623.26,4511.81 1645.89,4549.21
GPADC1: C136.2 R80.1 R316.1 U29.K2 | length 600
  SIG1 w6: v1(1890.73,3898.78) 1970.22,3819.3 v1(2032.05,3819.3)
  Bottom Layer w4: 2194.44,3913.25 2217.96,3913.25 2256.56,3913.25 2258.7,3911.11 2278.17,3911.11 U29.K2@2290.89,3923.84
  Bottom Layer w8: R316.1@1850.36,3979.4 1850.36,3961.75 1843.81,3955.21 R80.1@1843.81,3940.53 1844.8,3939.55 1844.8,3928.75 1850.36,3923.19 C136.2@1850.36,3906.58 1851.27,3905.67 1880.6,3905.67 1887.49,3898.78 v1(1890.73,3898.78) ; v1(2032.05,3819.3) 2050,3837.25 2064.25,3851.5 2070.75,3858 2122.32,3858 2139.13,3874.81 2156,3874.81 2194.44,3913.25
GPADC2: C135.2 R82.1 R315.1 U29.K1 | length 4138.7
  Top Layer w8: v1(686.42,1701) 686.42,1627.19 876.54,1437.07 876.54,1161.02 R315.1@905.35,1132.21
  PWR1 w15: v1(686.42,1701) 685.85,1701.57 661.3,1701.57 631.54,1731.33 631.54,1960 761,2089.46 761,2852.19 864.23,2955.42 864.23,3317.83 1398.4,3852 1710,3852 1742,3820 1847.38,3820 1851.19,3823.81 v1(1852,3823.81)
  Bottom Layer w4: 2150.19,3890 2184.28,3924.09 ccw(c2173,3936.81) 2185.4,3925.18 2185.92,3925.7 2263.44,3925.7 U29.K1@2265.3,3923.84
  Bottom Layer w8: C135.2@1852.47,3844.85 2027.04,3844.85 2053.69,3871.5 2116.73,3871.5 2135.23,3890 2150.19,3890
  Bottom Layer w10: R82.1@1843.81,3877.49 1844.6,3877.49 1852.47,3869.62 C135.2@1852.47,3844.85
  Bottom Layer w15: v1(1852,3823.81) 1852.24,3824.05 1852.24,3844.62 C135.2@1852.47,3844.85
GPADC3: C131.2 R83.1 R133.1 U29.N1 | length 3912.4
  Top Layer w8: v1(693.12,1726.97) 708.82,1742.67 R133.1@739.54,1742.67
  PWR1 w12: v1(693.12,1726.97) 691.97,1728.11 681.89,1728.11 659.81,1750.19 659.81,1937.53 816,2093.72 816,2852.59 890.79,2927.38 890.79,3316.81 926.49,3352.51 1404.79,3830.81 1697.19,3830.81 1731,3797 1867.66,3797 1874.69,3804.03 1874.69,3842.11 1844.3,3872.5 1844.3,4103.78 1853,4112.48 v1(1853,4113.81) 1908.5,4169.31 2124.61,4169.31 v1(2155.49,4138.43)
  Bottom Layer w4: v1(2155.49,4138.43) 2155,4137.93 2155,4093.97 2217.96,4031.01 2248.35,4000.61 U29.N1@2265.3,4000.61
  Bottom Layer w10: R83.1@1843.81,4035.43 1844.6,4035.43 1852.47,4043.31 C131.2@1852.47,4066.99
  Bottom Layer w15: C131.2@1852.47,4066.99 1852.74,4067.25 1852.74,4113.55 v1(1853,4113.81)
GPADC5: R91.1 U29.M2 | length 5021.4
  SIG1 w6: v1(460.37,991.86) 375.37,1076.86 375.37,1420.84 295,1501.21 295,1834.2 630.66,2169.86 1289.05,2169.86 1339.43,2220.24 1949.18,2220.24 2057.89,2328.95 v1(2057.89,2410)
  SIG2 w6: v1(2057.89,2410) 2057.89,2410.4 2067,2419.51 2067,2810 2086.06,2829.06 2086.06,2893.94 2080.25,2899.75 2080.25,3339.75 1889,3531 1889,3752.4 1926,3789.4 1926,3875 2040.81,3989.81 2050,3989.81 2175.16,3989.81 v1(2177,3991.64)
  Bottom Layer w4: v1(2177,3991.64) 2201.58,3991.64 2230.92,3962.3 2259.98,3962.3 2260.02,3962.26 2270.59,3962.26 2270.64,3962.31 2278.18,3962.31 U29.M2@2290.89,3975.02
  Bottom Layer w8: R91.1@408.15,979.39 447.9,979.39 v1(460.37,991.86)
GPADC6: R94.1 U29.L2 | length 482.5
  SIG1 w6: v1(1953.45,4007.81) 1972.19,4007.81 2020.76,3959.24 2050,3959.24 2184.18,3959.24 v1(2197.73,3945.69)
  Bottom Layer w4: v1(2197.73,3945.69) 2200.9,3945.69 2209.92,3936.67 2217.96,3936.67 2278.13,3936.67 U29.L2@2290.89,3949.43
  Bottom Layer w8: R94.1@1843.81,4009.45 1844.63,4008.63 1952.63,4008.63 v1(1953.45,4007.81)
GPIO_3: R219.1 R221.2 U29.L19 | length 1280.7
  SIG1 w6: v1(2523,3210.52) 2542,3229.52 2617.6,3229.52 2686.08,3298 2803.17,3298 2859.15,3353.98 2859.15,3536.81 2859.15,3742.01 2921.54,3804.4 2921.54,3833.46 2911.91,3843.09 2911.91,3926.89 v1(2923.02,3938)
  Bottom Layer w4: U29.L19@2725.93,3949.43 2738.8,3936.56 2744.66,3936.56 2777.6,3936.56 2777.67,3936.49
  Bottom Layer w6: 2777.67,3936.49 2796.72,3936.49 2806.24,3926.97 2908.74,3926.97 2919.77,3938 v1(2923.02,3938)
  Bottom Layer w8: R219.1@2495,3182.81 R221.2@2523,3182.81 v1(2523,3210.52)
GPIO_4: R228.2 U29.M19 | length 1314.9
  SIG1 w6: v1(2950.59,3336) 2950.89,3336 3193.25,3578.36 3193.25,3822.36 v1(3079.61,3936)
  Bottom Layer w4: U29.M19@2725.93,3975.02 2738.65,3962.3 2772.97,3962.3 2773.17,3962.49 2807.49,3962.49 2807.68,3962.3 2819.65,3962.3 2846.94,3989.58 2895.91,3989.58 2923.49,3962 2925.19,3962
  Bottom Layer w8: R228.2@2875,3192.81 2875,3260.41 v1(2950.59,3336) ; 2925.19,3962 2961.01,3962 2976.01,3947 3068.61,3947 v1(3079.61,3936)
GPIO_8: R233.1 R235.2 U29.M20 | length 1328.9
  SIG1 w6: v1(2948.77,3230) 2948.77,3307.61 3205.7,3564.54 3205.7,3844.38 3083.49,3966.59 3066.71,3966.59 v1(3065.49,3967.81)
  Bottom Layer w4: U29.M20@2751.52,3975.02 2818.94,3975.02 2843,3999.08 2902.71,3999.08 2922.79,3979 2925.19,3979
  Bottom Layer w8: R233.1@2912,3201.47 2916.64,3196.83 2927.33,3196.83 2931.35,3192.81 R235.2@2947.88,3192.81 ; 2925.19,3979 2967.07,3979 2982.61,3963.45 3057.89,3963.45 3062.24,3967.81 v1(3065.49,3967.81) ; R235.2@2947.88,3193.6 2948.77,3194.49 v1(2948.77,3230)
GPIO_9: R214.1 R217.2 U29.N20 | length 1389.4
  SIG1 w6: v1(2755.57,3228.89) 2785.7,3228.89 2954.97,3398.15 2979.1,3398.15 3169.25,3588.3 3169.25,3798.46 3011.79,3955.92 v1(3011.79,3999.81)
  Bottom Layer w4: 2923.42,4011 2925.19,4011
  Bottom Layer w4.19: U29.N20@2751.52,4000.61 2769.17,4000.61 2775.51,3994.27 2810.54,3994.27 2834.45,4018.18 2916.24,4018.18 2923.42,4011 ; 2925.19,4011 2925.19,4012.3
  Bottom Layer w8: v1(2755.57,3228.89) R214.1@2755.57,3201.47 2755.57,3198.81 2781.43,3198.81 2789.3,3190.94 R217.2@2789.3,3190.15 ; 2925.19,4012.3 2979.87,4012.3 2990.79,4001.38 3010.22,4001.38 v1(3011.79,3999.81)
HOSTIRQ_FTDI_IN: R151.1 U18.32 | length 200.3
  Bottom Layer w8: U18.32@1261.31,4528.19 1264.13,4531.01 R151.1@1460.43,4531.01
HOSTIRQ_FTDI_OUT: R153.1 U18.34 | length 141.8
  Bottom Layer w8: U18.34@1332.18,4437.64 1332.85,4438.31 1383.31,4438.31 1424.83,4479.83 R153.1@1456.49,4479.83
I2C_SCL_FTDI: R148.1 U18.26 | length 138.2
  Bottom Layer w8: R148.1@1111.81,4653.39 1143.2,4622 U18.26@1143.2,4528.19
I2C_SDA_FTDI_IN: R149.1 U18.27 | length 125.2
  Bottom Layer w8: U18.27@1162.88,4528.19 R149.1@1162.88,4653.39
I2C_SDA_FTDI_OUT: R150.1 U18.28 | length 138.2
  Bottom Layer w8: U18.28@1182.57,4528.19 1182.57,4619.43 R150.1@1215.81,4652.67
LVDS_TX0_N: R366.2 U29.D20 | length 5277.6
  Top Layer w4.8: R366.2@739.46,658.7 740.25,658.7 744.15,662.6 744.15,664.79 746.96,667.6 834,667.6 839.37,662.23 852.09,662.23 v1(854.61,659.7)
  SIG2 w4.8: v1(854.61,659.7) 857.02,659.7 864.02,666.7 2035.5,666.7 2155.34,786.55 2155.34,1010.67 2230.94,1086.27 2230.94,1900.61 2569.33,2239 2655.22,2239 2875.62,2459.4 2875.62,2524 2875.62,2556.72 2878.43,2559.53 2890.42,2559.53 2898.93,2568.04 2898.93,2589.82 2890.42,2598.33 2866.14,2598.33 2864.66,2599.81 2864.66,2611.65 2866.14,2613.13 2890.42,2613.13 2898.93,2621.64 2898.93,2643.42 2890.42,2651.93 2866.14,2651.93 2864.66,2653.41 2864.66,2665.25 2866.14,2666.73 2890.42,2666.73 2898.93,2675.24 2898.93,2697.02 2890.42,2705.53 2866.14,2705.53 2864.66,2707.01 2864.66,2718.85 2866.14,2720.33 2890.42,2720.33 2898.93,2728.84 2898.93,2750.62 2890.42,2759.13 2878.43,2759.13 2875.62,2761.94 2875.62,2837 2875.62,2903.24 2928.73,2956.36 2928.73,3421.28 2973.5,3466.05 2973.5,3526.97 2963.66,3536.81 2929.89,3536.81 2917.7,3524.62 v1(2917.7,3506)
  Bottom Layer w4.8: U29.D20@2751.52,3770.29 2752.32,3771.09 2762.6,3771.09 2780.79,3752.9 2843.16,3752.9 2885.58,3710.48 2885.58,3566.79 2915.56,3536.81 2925.6,3526.77 2925.6,3515.41 2917.7,3507.51 v1(2917.7,3506)
LVDS_TX0_P: R365.2 U29.D19 | length 5276.9
  Top Layer w4.8: R365.2@739.46,686.7 740.25,686.7 744.15,682.81 744.15,680.62 746.96,677.8 834,677.8 839.37,683.18 852.09,683.18 v1(854.61,685.7)
  SIG2 w4.8: v1(854.61,685.7) 857.02,685.7 864.02,678.7 879.71,678.7 891.01,690 904.51,690 915.81,678.7 2030.52,678.7 2143.34,791.52 2143.34,1015.65 2218.94,1091.25 2218.94,1905.58 2564.36,2251 2650.25,2251 2863.62,2464.37 2863.62,2524 2863.62,2561.69 2873.46,2571.53 2885.45,2571.53 2886.93,2573.01 2886.93,2584.85 2885.45,2586.33 2861.17,2586.33 2852.66,2594.84 2852.66,2616.62 2861.17,2625.13 2885.45,2625.13 2886.93,2626.61 2886.93,2638.45 2885.45,2639.93 2861.17,2639.93 2852.66,2648.44 2852.66,2670.22 2861.17,2678.73 2885.45,2678.73 2886.93,2680.21 2886.93,2692.05 2885.45,2693.53 2861.17,2693.53 2852.66,2702.04 2852.66,2723.82 2861.17,2732.33 2885.45,2732.33 2886.93,2733.81 2886.93,2745.65 2885.45,2747.13 2873.46,2747.13 2863.62,2756.97 2863.62,2837 2863.62,2908.21 2916.73,2961.33 2916.73,3426.25 2961.5,3471.02 2961.5,3522 2958.69,3524.81 2934.86,3524.81 2934.86,3518.41 2943.7,3509.57 v1(2943.7,3506)
  Bottom Layer w4: U29.D19@2725.93,3770.29 2738.65,3783.02 2756.79,3783.02
  Bottom Layer w4.8: 2756.79,3783.02 2765.1,3783.02 2785.01,3763.1 2847.38,3763.1 2895.78,3714.7 2895.78,3571.01 2935.8,3530.99 2935.8,3515.41 2943.7,3507.51 v1(2943.7,3506)
LVDS_TX1_N: R364.2 U29.H20 | length 5276.3
  Top Layer w4.8: R364.2@739.46,717.76 740.25,717.76 744.15,721.66 744.15,723.85 746.96,726.66 756.55,726.66 764.45,718.76 v1(768.02,718.76)
  SIG2 w4.8: v1(768.02,718.76) 775.02,725.76 968.42,725.76 996.08,698.1 2006.99,698.1 2113.77,804.89 2113.77,1027.3 2191.44,1104.97 2191.44,1905.93 2566.51,2281 2624.62,2281 2788.57,2444.95 2788.57,2885.96 2886.59,2983.98 2886.59,3533.57 2907.36,3554.34 2907.36,3700.33 2985.03,3778 3027.8,3778 3069.83,3820.03 3069.83,3851.16 3059.99,3861 3028.36,3861 3024.89,3864.47 3011.72,3864.47 v1(3009.19,3867)
  Bottom Layer w4.8: U29.H20@2751.52,3872.66 2753.23,3870.95 2765.31,3870.95 2767.99,3868.27 2777.66,3868.27 2823.62,3868.28 2828.63,3863.27 2892.81,3863.27 2896.98,3859.1 2999.78,3859.1 3007.68,3867 v1(3009.19,3867)
LVDS_TX1_P: R363.2 U29.H19 | length 5268.2
  Top Layer w4.8: R363.2@739.46,745.76 740.25,745.76 744.15,741.86 744.15,739.67 746.96,736.86 756.55,736.86 764.45,744.76 v1(768.02,744.76)
  SIG2 w4.8: v1@770.05,737.76 794.9,737.76 802.14,745 810.97,745 818.21,737.76 973.39,737.76 1001.05,710.1 2002.02,710.1 2101.77,809.86 2101.77,1032.27 2179.44,1109.94 2179.44,1910.9 2561.54,2293 2619.65,2293 2776.57,2449.92 2776.57,2890.93 2874.59,2988.95 2874.59,3538.54 2895.36,3559.31 2895.36,3705.3 2980.06,3790 3022.83,3790 3057.83,3825 3057.83,3846.19 3055.02,3849 3030.36,3849 3024.89,3843.53 3011.72,3843.53 v1(3009.19,3841)
  Bottom Layer w4: U29.H19@2725.93,3872.66 2728.4,3872.66 2741.27,3859.79 2756.79,3859.79 2758.49,3858.09 2777.66,3858.09
  Bottom Layer w4.8: 2777.68,3858.07 2819.4,3858.07 2824.4,3853.07 2888.58,3853.07 2892.76,3848.9 2999.78,3848.9 3007.68,3841 v1(3009.19,3841)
